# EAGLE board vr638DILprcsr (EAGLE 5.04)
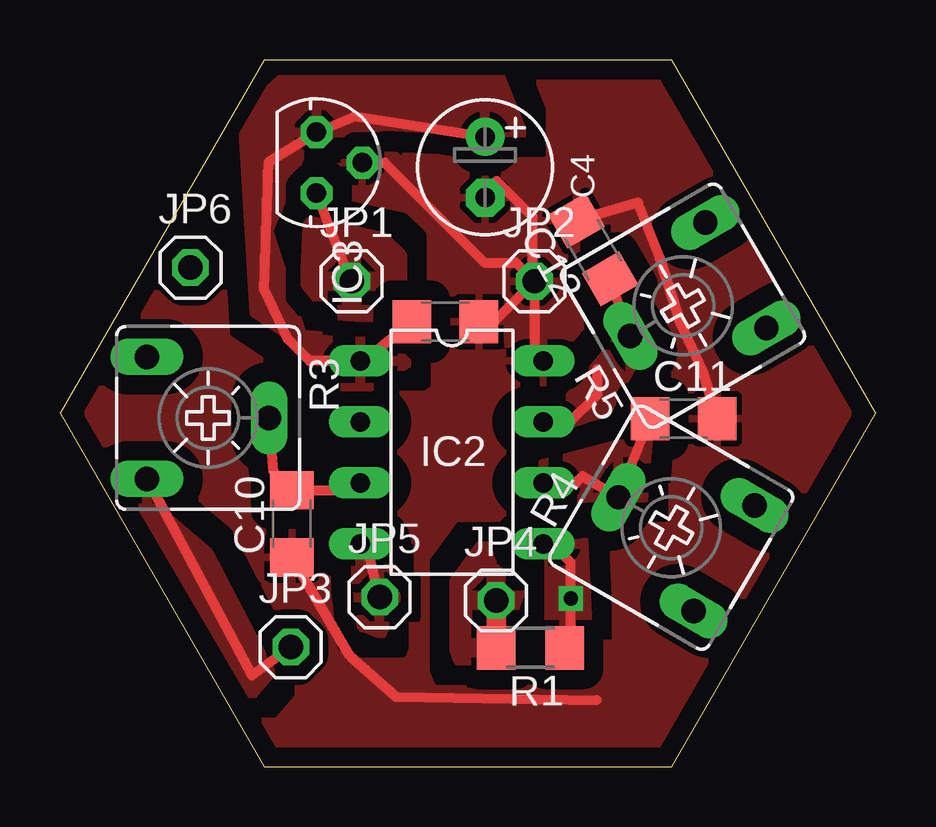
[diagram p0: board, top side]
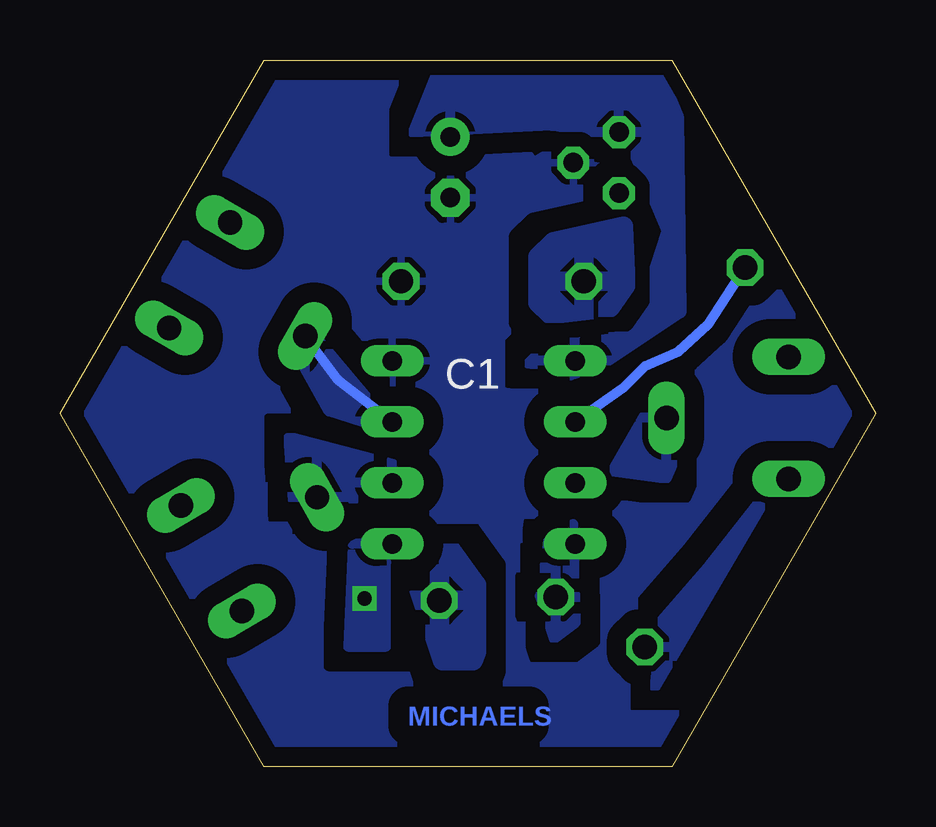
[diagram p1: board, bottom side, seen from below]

Size 34 x 29.44 mm. Coordinates in mm from the lower left corner, seen from the top.
Outline: 8.5,0 25.5,0 34,14.72 25.5,29.44 8.5,29.44 0,14.72 8.5,0
Copper layers (1*16): Top 0.035mm / dielectric 1.5mm / Bottom 0.035mm
Design rules "default *": minimum track width 10mil, minimum drill 24mil, track to track 8mil, track to pad 8mil, pad to pad 8mil, via to via 8mil, smd to smd 8mil, copper to edge 10mil, drill to drill 8mil, minimum pad ring 10mil, minimum via ring 8mil, stop-mask expansion 4mil, vias tented up to drill 0mil, thermal gap 10mil

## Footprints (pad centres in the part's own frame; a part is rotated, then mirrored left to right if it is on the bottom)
C1206 = smd 1.6 x 1.8: 1 -1.4,0; 2 1.4,0
E2,5-6 = drill 0.813 pad 1.6 round: + -1.27,0 | drill 0.813 pad 1.6 octagon: - 1.27,0
DIL8 = drill 0.813 long: 1 -3.81,-3.81; 2 -1.27,-3.81; 3 1.27,-3.81; 4 3.81,-3.81; 5 3.81,3.81; 6 1.27,3.81; 7 -1.27,3.81; 8 -3.81,3.81
78LXX = drill 0.813 octagon: GND 0,1.905; IN 1.27,0; OUT -1.27,0
1X01 = drill 1.016 octagon: 1 0,0
R1206 = smd 1.6 x 1.803: 1 -1.422,0; 2 1.422,0
CA6V = drill 1.016 long: A -2.54,-2.54; E 2.54,-2.54; S 0,2.54

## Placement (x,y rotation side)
C1  0u1  [C1206]  16.06,18.54 180 top
C4  47u 10  [E2,5-6]  17.72,24.97 270 top
C10  0u1  [C1206]  9.67,10.11 90 top
C11  0u1  [C1206]  26,14.49 0 top
C12  0u1  [C1206]  22.23,21.53 120 top
IC2  PIC12F675P  [DIL8]  16.34,13.09 270 top
IC3  [78LXX]  10.7,25.16 270 top
JP1  [1X01]  12.16,20.22 0 top
JP2  [1X01]  19.78,20.22 0 top
JP3  [1X01]  9.62,4.98 0 top
JP4  [1X01]  18.18,6.92 0 top
JP5  [1X01]  13.33,7.06 0 top
JP6  [1X01]  5.44,20.79 0 top
R1  150k  [R1206]  19.61,4.95 180 top
R3  [CA6V]  6.17,14.53 270 top
R4  [CA6V]  25.48,9.95 60 top
R5  [CA6V]  25.98,19.2 120 top

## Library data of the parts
C1 C4 C10-C12 R1 = rcl
IC2 = microchip-3
IC3 = v-reg
JP1-JP6 = pinhead
R3-R5 = pot

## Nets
N$1: JP3.1 R3.E
N$2: JP4.1 R1.2
N$3: IC2.4 JP5.1
N$4: IC2.2 JP6.1
N$5: IC2.5 R1.1
N$12: C10.2 IC2.3 R3.S
N$13: C12.1 IC2.7 R5.S
N$15: C11.1 IC2.6 R4.S
N$20: IC3.IN JP1.1
V+: C1.2 C4.+ IC2.1 IC3.OUT
V-: C1.1 C4.- C10.1 C11.2 C12.2 IC2.8 IC3.GND JP2.1

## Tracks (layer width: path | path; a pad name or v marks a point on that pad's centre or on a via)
N$1
  Top 0.406: JP3.1 8,3.8 R3.E
  pour Top (isolate 0.61): 2.9,11.7 8,3 8.8,3.9 6.2,8.9
  pour Bottom (isolate 0.61): 4.1,12 9.2,3.3 8.9,6.1 7,8.3
N$2
  Top 0.813: R1.2 JP4.1
  pour Top (isolate 0.813): 18.05,4.51 16.78,4.51 16.63,4.89 16.63,7.68 17.93,9.46 18.18,9.46 19.32,8.32
  pour Bottom (isolate 0.813): 18.05,4.41 16.78,4.41 16.63,4.79 16.63,7.58 17.93,9.36 18.18,9.36 19.32,8.22
N$3
  Top 0.406: IC2.4 12.83,9.06 JP5.1
  Bottom 0.406: JP5.1 13.3,7.49
  pour Top (isolate 0.254): 12.3,8.5 13.6,8.9 14,7 13.4,5.5 12.6,5.8
  pour Bottom (isolate 0.61): 12.6,10.1 13.6,9.8 14,7.1 13.4,5.3 12.5,6
N$4
  Bottom 0.406: IC2.2 10.5,15.8 9.6,16.7 8.2,17.3 7,18.4 JP6.1
N$5  (via drill 0.6)
  Top 0.406: IC2.5 20.52,9.28 21.3,8.5 v21.3,7 21.3,5.21 R1.1
  pour Top (isolate 0.61): 21,10 21.8,9.6 22,5.4 20.4,5.4 20.4,8.9
  pour Bottom (isolate 0.254): 21,9.6 21.8,9.2 22,5 20.4,5 20.4,8.5
N$12
  Top 0.406: R3.S 8.91,12.27 C10.2 12.22,11.51 IC2.3
  pour Bottom (isolate 0.61): 9.5,14.9 11,12.3 8.7,12 7.9,13.8
N$13
  Top 0.406: R5.S C12.1 | IC2.7 21.26,14.36 22.4,15.5 22.4,16.56
  Bottom 0.406: R5.S 22.4,16.1 IC2.7
  pour Top (isolate 0.61): 20.9,14.2 22.8,14.8 24.3,17.5 23.5,18.1 20.3,14.3
  pour Bottom (isolate 0.406): 20.9,14.2 22.8,14.8 24.3,17.5 23.5,18.1 20.3,14.3
N$15
  Top 0.406: C11.1 R4.S 21.8,12.1 21.52,11.82 IC2.6
  pour Top (isolate 0.61, rank 2): 20.1,12.6 24.3,13.7 24.5,13.7 24.3,11.1 23.6,10.7 20.7,11.4
  pour Bottom (isolate 0.61, rank 2): 20.1,12.6 24.3,13.7 24.5,13.7 24.3,11.1 23.6,10.7 20.7,11.4
N$20
  Top 0.406: IC3.IN 12.1,20.28 JP1.1
  pour Top (isolate 0.813): 10.51,22.51 10.41,20.18 11.36,19.02 13.56,18.82 14.06,19.33 14.06,21.24 13.43,21.87
  pour Bottom (isolate 0.813): 10.51,22.51 10.41,20.08 11.06,19.12 13.56,18.82 14.06,19.33 14.06,21.24 13.43,21.87
V+
  Top 0.406: C4.+ 12.3,27.1 IC3.OUT 8.7,25.2 8.5,19.9 9.5,17.8 10.4,16.9 IC2.1 12.59,16.84 C1.2
  pour Top (isolate 0.61, rank 2): 18.3,28.9 9.6,29 7.6,27.2 8.1,18.9 11.4,16.7 12.1,15.3 14.5,16.8 13.6,17.7 10.1,18 8.7,22.3 10.3,26.1 13.5,26.7 19.3,26.4
  pour Bottom (isolate 0.61, rank 2): 18.3,28.9 8.9,28.8 8.2,27.1 8.1,18.9 11.4,16.7 12.7,16.3 14.5,16.8 13.6,17.7 10.1,18 8.7,22.3 10.3,26.1 13.5,26.7 19.3,26.4
V-
  Top 0.406: IC3.GND 13.54,25.16 17.7,21 19,21 JP2.1 | C4.- 18.2,24.4 19.7,22.9 19.7,20.3 JP2.1 | C11.2 26.8,16.5 25.9,18.4 25,21.2 24.1,23.5 C12.2 | C10.1 12.1,4.6 14,2.9 22.37,2.77 | JP2.1 19.78,17.27 IC2.8 | C1.1 17.76,18.2 JP2.1
  pour Top (isolate 0.813, rank 4): 14.24,25.25 17.43,29.55 26.6,29.18 28.38,24.21 33.66,14.78 25.09,0.25 9.24,0.25 0.42,14.47 5.82,25.54 8.51,30.44
  pour Bottom (isolate 0.813, rank 4): 14.24,25.25 17.43,29.55 26.6,29.18 28.38,24.21 33.16,14.78 24.79,0.45 9.34,0.45 0.32,14.67 6.02,23.74 8.71,28.64

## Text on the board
Bottom: MICHAELS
